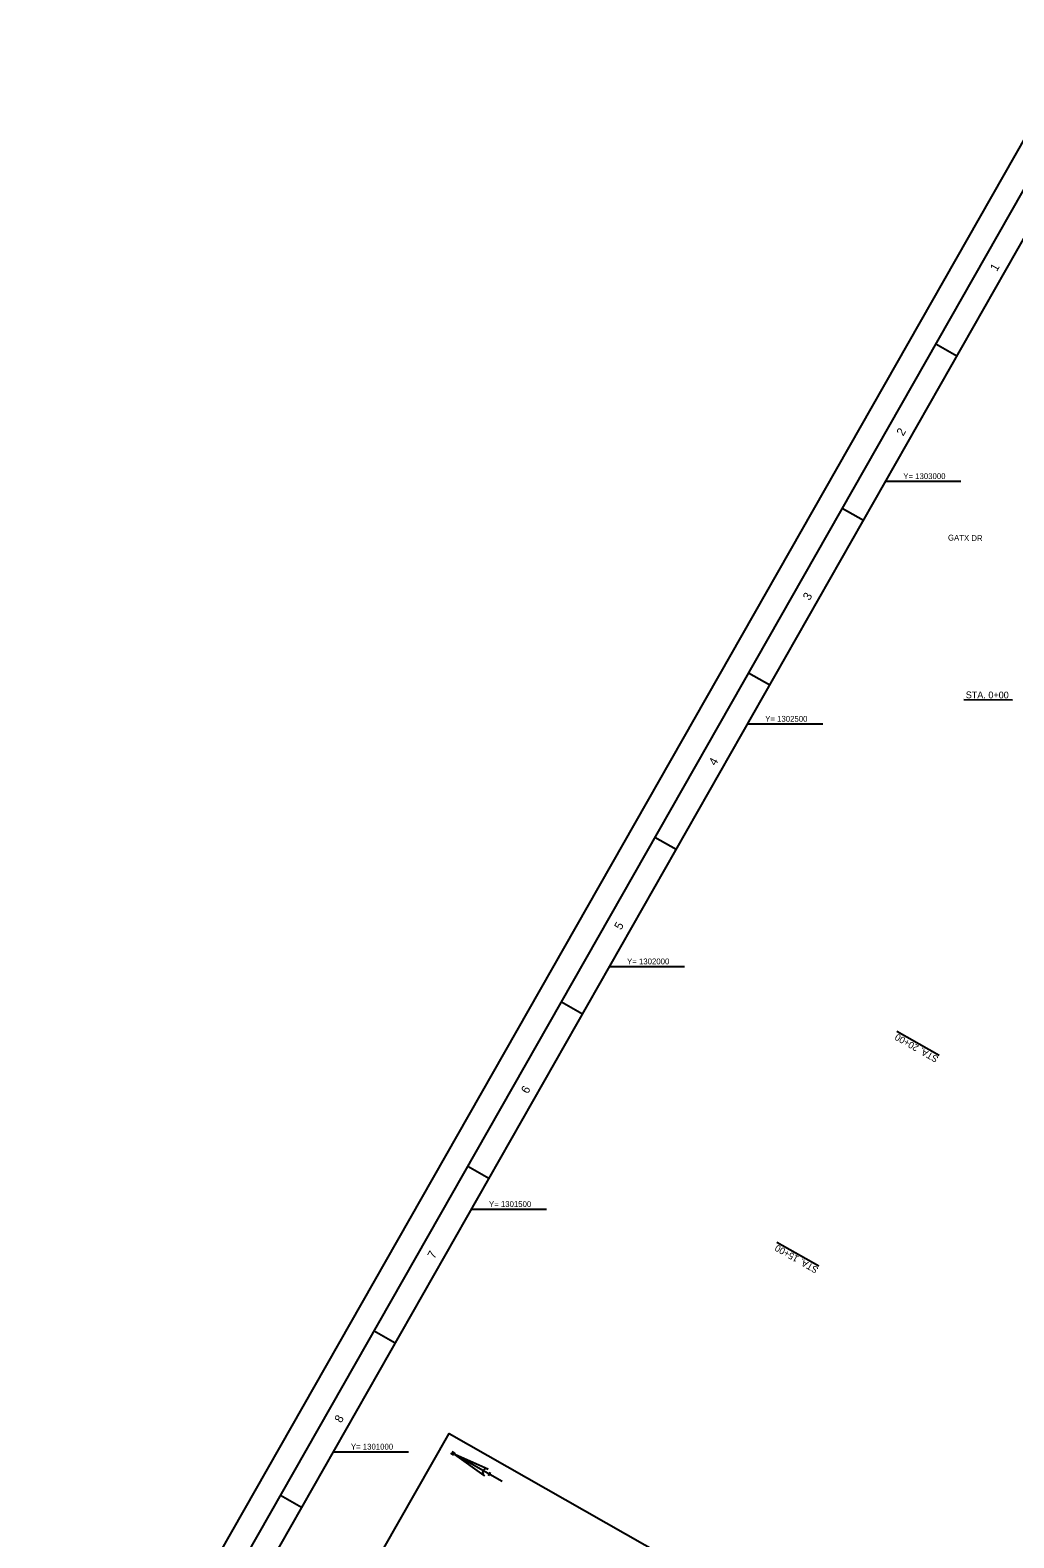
# Model space of a CAD drawing. Extents: x 515534 to 520665, y 1298425 to 1303930.
# Drawn here: x 515534 to 517560, y 1300823 to 1303930 of the extents above; entities that cross this region are included whole.
import ezdxf

# ---------------------------------------------------------------- set-up
doc = ezdxf.new("R2010")
doc.units = 0
for name, color, linetype in [('G-ANNO-NPLT', 7, 'Continuous'), ('G-ANNO-TTLB', 7, 'Continuous'), ('V-ALGN-TEXT', 7, 'Continuous'), ('V-ANNO-SYMB', 7, 'Continuous'), ('V-ROAD-IDEN', 7, 'Continuous'), ('V-TOPO-COOR-STAT', 7, 'Continuous')]:
    doc.layers.add(name, color=color, linetype=linetype)

msp = doc.modelspace()

# ---------------------------------------------------------------- linework, layer by layer
at = {"layer": 'G-ANNO-NPLT'}
msp.add_lwpolyline([(515533.7, 1300105.7), (517709.3, 1303930.2), (520664.6, 1302249.1), (518489, 1298424.6)], close=True, dxfattribs=at)
at = {"layer": 'G-ANNO-TTLB'}
for p, q in [((517399.2, 1303284), (517442.7, 1303259.3)), ((517206.4, 1302945), (517249.9, 1302920.3)), ((517013.6, 1302606), (517057, 1302581.3)), ((516820.7, 1302267), (516864.2, 1302242.3)), ((516627.9, 1301928), (516671.4, 1301903.3)), ((516435.1, 1301589), (516478.5, 1301564.3)), ((516242.2, 1301250), (516285.7, 1301225.3)), ((516049.4, 1300911), (516092.9, 1300886.3)), ((516049.4, 1300911), (516092.9, 1300886.3))]:
    msp.add_line(p, q, dxfattribs=at)
for points in [[(518470.3, 1298492.8), (520596.4, 1302230.3), (517728, 1303862), (515601.9, 1300124.4)], [(517746.8, 1303793.8), (515707.2, 1300208.3), (518488.6, 1298626.1), (520528.2, 1302211.6)]]:
    msp.add_lwpolyline(points, close=True, dxfattribs=at)
at = {"layer": 'V-ALGN-TEXT'}
for p, q in [((517457.1, 1302550.7), (517557.1, 1302550.3)), ((517405.7, 1301817.3), (517318.8, 1301866.7)), ((517158.5, 1301382.7), (517071.6, 1301432.1))]:
    msp.add_line(p, q, dxfattribs=at)
at = {"layer": 'V-ANNO-SYMB'}
for p, q in [((516505.6, 1300939.5), (516408.5, 1300994.7)), ((516476.2, 1300964.7), (516408.5, 1300994.7)), ((516468.9, 1300951.9), (516408.5, 1300994.7)), ((516481.1, 1300957.5), (516477.4, 1300951))]:
    msp.add_line(p, q, dxfattribs=at)
msp.add_lwpolyline([(516091.4, 1300501.5), (516396.7, 1301038), (516998.6, 1300695.6), (516693.4, 1300159.1)], close=True, dxfattribs=at)
msp.add_lwpolyline([(516406.4, 1300993.5), (516400.8, 1300996.8), (516408.4, 1300997.1), (516402.8, 1301000.3)], dxfattribs=at)
msp.add_arc((516473.2, 1300957.9), 7.45, 55.6651, 242.434, dxfattribs=at)
at = {"layer": 'V-TOPO-COOR-STAT'}
for p, q in [((517450.5, 1303000), (517295.2, 1303000)), ((517166.1, 1302500), (517010.8, 1302500)), ((516881.7, 1302000), (516726.4, 1302000)), ((516597.3, 1301500), (516442, 1301500)), ((516312.8, 1301000), (516157.5, 1301000))]:
    msp.add_line(p, q, dxfattribs=at)

# ---------------------------------------------------------------- texts
at = {"layer": 'G-ANNO-TTLB'}
for s, p in [('1', (517524.8, 1303431.6)), ('2', (517332, 1303092.6)), ('3', (517139.1, 1302753.6)), ('4', (516945.4, 1302413.1)), ('5', (516750.8, 1302074.7)), ('6', (516558.7, 1301737)), ('7', (516366, 1301396.9)), ('8', (516174.4, 1301058.7))]:
    msp.add_text(s, height=17.5, rotation=60.3667, dxfattribs=at).set_placement(p)
at = {"layer": 'V-ALGN-TEXT'}
for s, rotation, p in [('STA. 0+00', 359.7829, (517460.8, 1302553.4)), ('STA. 20+00', 150.3667, (517405.8, 1301814)), ('STA. 15+00', 150.3667, (517158.6, 1301379.4))]:
    msp.add_text(s, height=13.92, rotation=rotation, dxfattribs=at).set_placement(p)
at = {"layer": 'V-ROAD-IDEN'}
msp.add_text('GATX DR', height=12, rotation=359.0405, dxfattribs=at).set_placement((517424.1, 1302878.4))
at = {"layer": 'V-TOPO-COOR-STAT'}
for s, p in [('Y= 1303000', (517332.1, 1303005)), ('Y= 1302500', (517047.7, 1302505)), ('Y= 1302000', (516763.2, 1302005)), ('Y= 1301500', (516478.8, 1301505)), ('Y= 1301000', (516194.4, 1301005))]:
    msp.add_text(s, height=12, dxfattribs=at).set_placement(p)

doc.saveas('drawing.dxf')
